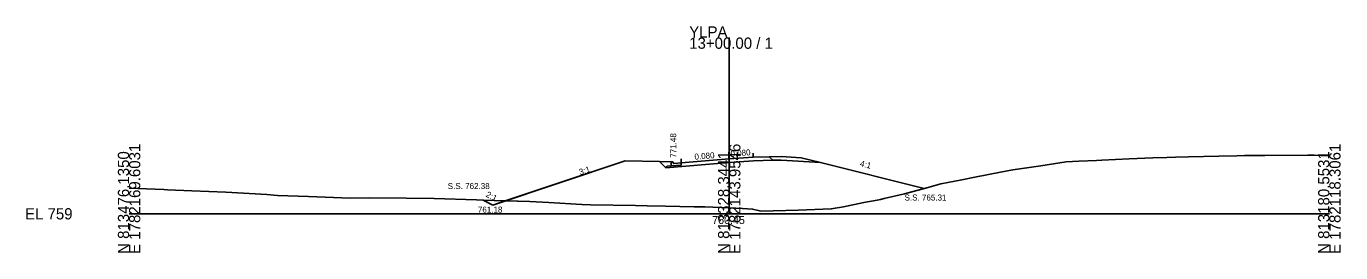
# Model space of a CAD drawing. Extents: x -76 to 1303, y -10 to 9544.
# Drawn here: x -25.7 to 302.8, y 2990.3 to 3046.8 of the extents above; entities that cross this region are included whole.
import ezdxf

# ---------------------------------------------------------------- set-up
doc = ezdxf.new("R2010")
doc.units = 0
for name, color, linetype in [('Exist Cross Section Cell', 7, 'Continuous'), ('Exist XS Center Line Elevation Label', 7, 'Continuous'), ('Exist XS Ground Line', 7, 'Continuous'), ('Prop XS Ditch Standard Text', 7, 'Continuous'), ('Prop XS Dump Level', 7, 'Continuous'), ('Prop XS Earthwork Shape', 7, 'Continuous'), ('Prop XS EOT Tick Mark', 7, 'Continuous'), ('Prop XS Finish Grade', 7, 'Continuous'), ('Prop XS Finish Grade CurbGutter', 7, 'Continuous'), ('Prop XS Finish Grade Earthwork', 7, 'Continuous'), ('Prop XS Finish Grade Paved Shoulder', 7, 'Continuous'), ('Prop XS Finish Grade Pavement', 7, 'Continuous'), ('Prop XS Hydro Elevations', 7, 'Continuous'), ('Prop XS Pvmt Edge Slope', 7, 'Continuous'), ('Prop XS SE Text', 7, 'Continuous'), ('Prop XS Side Slope Text', 7, 'Continuous'), ('Prop XS SS Elevation Text', 7, 'Continuous'), ('Prop XS Subgrade CurbGutter', 7, 'Continuous'), ('Prop XS Subgrade Earthwork', 7, 'Continuous'), ('Scratch_Level_3', 7, 'Continuous')]:
    doc.layers.add(name, color=color, linetype=linetype)

msp = doc.modelspace()

# ---------------------------------------------------------------- linework, layer by layer
at = {"layer": 'Exist Cross Section Cell'}
for p, q in [((150, 3000), (150, 3043.96)), ((0, 3000), (150, 3000)), ((150, 3000), (300, 3000))]:
    msp.add_line(p, q, dxfattribs=at)
at = {"layer": 'Exist XS Ground Line'}
for p, q in [((227.85, 3011.98), (234.18, 3012.93)), ((234.18, 3012.93), (237.36, 3013.12)), ((237.36, 3013.12), (241.83, 3013.32)), ((241.83, 3013.32), (243.12, 3013.39)), ((243.12, 3013.39), (249.98, 3013.72)), ((249.98, 3013.72), (255.9, 3013.94)), ((255.9, 3013.94), (259.4, 3014.08)), ((259.4, 3014.08), (261.54, 3014.16)), ((261.54, 3014.16), (264.78, 3014.23)), ((264.78, 3014.23), (272.38, 3014.38)), ((272.38, 3014.38), (276.87, 3014.47)), ((276.87, 3014.47), (278.83, 3014.51)), ((278.83, 3014.51), (283.89, 3014.55)), ((283.89, 3014.55), (294.59, 3014.65)), ((294.59, 3014.65), (296.19, 3014.6)), ((296.19, 3014.6), (299.7, 3014.48)), ((299.7, 3014.48), (300, 3014.46)), ((211.35, 3009.14), (217.77, 3010.36)), ((217.77, 3010.36), (220.9, 3010.93)), ((220.9, 3010.93), (227.85, 3011.98)), ((0, 3006.39), (8.69, 3006.06)), ((193.83, 3004.97), (199.36, 3006.48)), ((199.36, 3006.48), (202.89, 3007.46)), ((202.89, 3007.46), (208.15, 3008.45)), ((208.15, 3008.45), (211.35, 3009.14)), ((8.69, 3006.06), (9.62, 3006.01)), ((9.62, 3006.01), (15.67, 3005.76)), ((15.67, 3005.76), (24.22, 3005.43)), ((24.22, 3005.43), (34.39, 3004.8)), ((34.39, 3004.8), (37.06, 3004.58)), ((37.06, 3004.58), (44.84, 3004.34)), ((44.84, 3004.34), (55.24, 3003.94)), ((55.24, 3003.94), (60.11, 3004)), ((60.11, 3004), (69.24, 3003.94)), ((69.24, 3003.94), (76.27, 3003.81)), ((76.27, 3003.81), (86.81, 3003.47)), ((86.81, 3003.47), (88.5, 3003.38)), ((88.5, 3003.38), (100.2, 3003.07)), ((100.2, 3003.07), (104.94, 3002.78)), ((178.56, 3001.77), (183.65, 3002.8)), ((183.65, 3002.8), (186.96, 3003.39)), ((186.96, 3003.39), (187.78, 3003.56)), ((187.78, 3003.56), (188.75, 3003.82)), ((188.75, 3003.82), (193.83, 3004.97)), ((104.94, 3002.78), (113.17, 3002.3)), ((113.17, 3002.3), (115.29, 3002.23)), ((115.29, 3002.23), (126.56, 3002.05)), ((126.56, 3002.05), (129.47, 3001.97)), ((129.47, 3001.97), (134.06, 3001.9)), ((134.06, 3001.9), (141.28, 3001.77)), ((141.28, 3001.77), (143.89, 3001.74)), ((143.89, 3001.74), (150, 3001.45)), ((150, 3001.45), (153.28, 3001.3)), ((153.28, 3001.3), (155.84, 3001.16)), ((155.84, 3001.16), (157.24, 3000.83)), ((157.24, 3000.83), (157.92, 3000.66)), ((157.92, 3000.66), (167.25, 3000.87)), ((167.25, 3000.87), (175.52, 3001.2)), ((175.52, 3001.2), (178.56, 3001.77))]:
    msp.add_line(p, q, dxfattribs=at)
at = {"layer": 'Prop XS Dump Level'}
for p, q in [((138, 3012.72), (150, 3013.68)), ((150, 3013.68), (156, 3014.16))]:
    msp.add_line(p, q, dxfattribs=at)
at = {"layer": 'Prop XS Earthwork Shape'}
for points in [[(160.9, 3013.34), (162.98, 3013.38), (172.83, 3012.79), (198.76, 3006.31), (193.83, 3004.97), (188.75, 3003.82), (187.78, 3003.56), (186.96, 3003.39), (183.65, 3002.8), (178.56, 3001.77), (175.52, 3001.2), (167.25, 3000.87), (157.92, 3000.66), (157.24, 3000.83), (155.84, 3001.16), (153.28, 3001.3), (150, 3001.45), (143.89, 3001.74), (141.28, 3001.77), (134.06, 3001.9), (129.47, 3001.97), (126.56, 3002.05), (115.29, 3002.23), (113.17, 3002.3), (104.94, 3002.78), (100.2, 3003.07), (94.03, 3003.23), (124, 3013.22), (132.61, 3013.04), (134.16, 3011.49), (150.07, 3012.77), (156.05, 3013.24)], [(90.88, 3002.18), (88.48, 3003.38), (88.5, 3003.38), (94.03, 3003.23)]]:
    msp.add_lwpolyline(points, close=True, dxfattribs=at)
at = {"layer": 'Prop XS EOT Tick Mark'}
for p, q in [((138, 3012.72), (138, 3013.72)), ((156, 3014.16), (156, 3015.16))]:
    msp.add_line(p, q, dxfattribs=at)
at = {"layer": 'Prop XS Finish Grade'}
for p, q in [((135.5, 3012.98), (132.61, 3013.04)), ((160, 3014.24), (163, 3014.3)), ((163, 3014.3), (168, 3014)), ((168, 3014), (172.83, 3012.79))]:
    msp.add_line(p, q, dxfattribs=at)
at = {"layer": 'Prop XS Finish Grade CurbGutter'}
for p, q in [((135.5, 3012.98), (135.75, 3012.98)), ((135.75, 3012.98), (135.88, 3012.97)), ((135.97, 3012.88), (135.88, 3012.97)), ((136.03, 3012.63), (135.97, 3012.88)), ((138, 3012.72), (136.25, 3012.51)), ((136.13, 3012.53), (136.03, 3012.63)), ((136.25, 3012.51), (136.13, 3012.53))]:
    msp.add_line(p, q, dxfattribs=at)
at = {"layer": 'Prop XS Finish Grade Earthwork'}
for p, q in [((124, 3013.22), (90.88, 3002.18)), ((132.61, 3013.04), (124, 3013.22)), ((172.83, 3012.79), (198.76, 3006.31)), ((90.88, 3002.18), (88.48, 3003.38))]:
    msp.add_line(p, q, dxfattribs=at)
at = {"layer": 'Prop XS Finish Grade Paved Shoulder'}
msp.add_line((156, 3014.16), (160, 3014.24), dxfattribs=at)
at = {"layer": 'Prop XS Finish Grade Pavement'}
for p, q in [((138, 3012.72), (150, 3013.68)), ((150, 3013.68), (156, 3014.16))]:
    msp.add_line(p, q, dxfattribs=at)
at = {"layer": 'Prop XS Pvmt Edge Slope'}
for p, q in [((160, 3014.24), (160.9, 3013.34)), ((134.5, 3011.86), (134.16, 3011.49)), ((135.5, 3011.94), (134.5, 3011.86))]:
    msp.add_line(p, q, dxfattribs=at)
at = {"layer": 'Prop XS Subgrade CurbGutter'}
for p, q in [((135.5, 3011.94), (135.5, 3012.98)), ((138, 3012.72), (138, 3012.14)), ((138, 3012.14), (135.5, 3011.94))]:
    msp.add_line(p, q, dxfattribs=at)
at = {"layer": 'Prop XS Subgrade Earthwork'}
for p, q in [((134.16, 3011.49), (132.61, 3013.04)), ((134.16, 3011.49), (150.07, 3012.77)), ((150.07, 3012.77), (156.05, 3013.24)), ((156.05, 3013.24), (160.9, 3013.34)), ((160.9, 3013.34), (162.98, 3013.38)), ((162.98, 3013.38), (172.83, 3012.79))]:
    msp.add_line(p, q, dxfattribs=at)
at = {"layer": 'Scratch_Level_3'}
for p, q in [((163, 3014.3), (160, 3014.24)), ((160, 3014.24), (160.9, 3013.34)), ((160.9, 3013.34), (162.98, 3013.38)), ((162.98, 3013.38), (172.83, 3012.79)), ((168, 3014), (163, 3014.3)), ((172.83, 3012.79), (168, 3014))]:
    msp.add_line(p, q, dxfattribs=at)

# ---------------------------------------------------------------- texts
at = {"layer": 'Exist Cross Section Cell'}
for s, p in [('YLPA', (140, 3043.96)), ('13+00.00 / 1', (140, 3041.16)), ('EL 759', (-26, 2998.6))]:
    msp.add_text(s, height=2.8, dxfattribs=at).set_placement(p)
for s, p in [('E 1782169.6031', (2.8, 2990)), ('E 1782143.9546', (152.8, 2990)), ('E 1782118.3061', (302.8, 2990)), ('N 813476.1350', (0, 2990)), ('N 813328.3441', (150, 2990)), ('N 813180.5531', (300, 2990))]:
    msp.add_text(s, height=2.8, rotation=90, dxfattribs=at).set_placement(p)
at = {"layer": 'Exist XS Center Line Elevation Label'}
msp.add_text('760.45', height=2, dxfattribs=at).set_placement((145.74, 2997.45))
at = {"layer": 'Prop XS Ditch Standard Text'}
msp.add_text('761.18', height=1.5, dxfattribs=at).set_placement((87.18, 3000.3))
at = {"layer": 'Prop XS Dump Level'}
msp.add_text('Case4', height=0.04, dxfattribs=at).set_placement((168, 3013.96))
at = {"layer": 'Prop XS Hydro Elevations'}
msp.add_text('771.48', height=1.5, rotation=90, dxfattribs=at).set_placement((136.75, 3013.98))
at = {"layer": 'Prop XS SE Text'}
for p in [(150.38, 3014.21), (141.38, 3013.49)]:
    msp.add_text('0.080', height=1.5, rotation=4.5739, dxfattribs=at).set_placement(p)
at = {"layer": 'Prop XS Side Slope Text'}
for s, rotation, p in [('4:1', 345.9638, (182.57, 3011.9)), ('3:1', 17.8228, (112.73, 3009.63)), ('2:1', 333.4349, (89.03, 3004.33))]:
    msp.add_text(s, height=1.5, rotation=rotation, dxfattribs=at).set_placement(p)
at = {"layer": 'Prop XS SS Elevation Text'}
for s, p in [('S.S. 762.38', (79.65, 3006.17)), ('S.S. 765.31', (193.83, 3003.31))]:
    msp.add_text(s, height=1.5, dxfattribs=at).set_placement(p)

doc.saveas('drawing.dxf')
